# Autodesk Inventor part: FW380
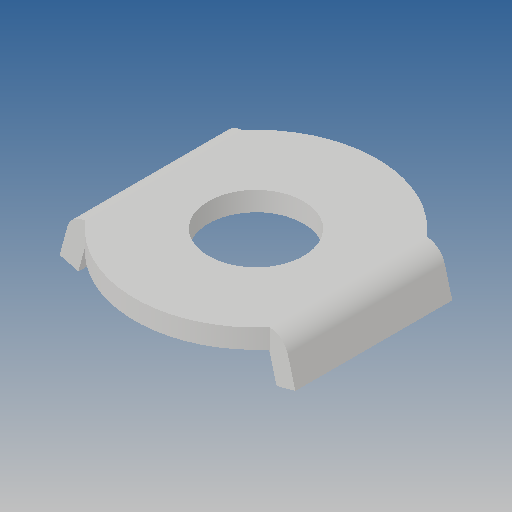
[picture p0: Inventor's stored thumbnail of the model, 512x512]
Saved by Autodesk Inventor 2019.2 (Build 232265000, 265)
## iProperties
Created: 2012-09
Part Number: FW380
Material: Ogólny
Document SubType Name: Modeling
Designer: CADENGINEERING4
Density: 1 g/cm^3
Appearance: Domyślna
Author: CADENGINEERING4
Revision Number: ÈÎºÎ
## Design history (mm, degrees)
feature "ÇÐ³ý-À­Éì1"
node "Bryła1"
